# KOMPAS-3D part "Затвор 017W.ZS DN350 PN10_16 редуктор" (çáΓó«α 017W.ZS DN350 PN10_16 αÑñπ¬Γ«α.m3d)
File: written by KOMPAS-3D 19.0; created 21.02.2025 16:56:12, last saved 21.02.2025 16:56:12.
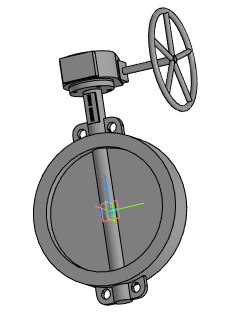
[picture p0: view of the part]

Document properties: Автор: Евгений; Полное имя файла: Затвор 017W.ZS DN350 PN10_16 редуктор.a3d

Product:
- Part/product: Затвор 017W.ZS DN350 PN10_16 редуктор
    Масса: 70.1889

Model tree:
1. Операция без истории:1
